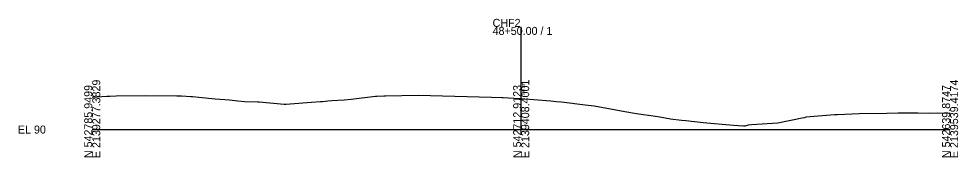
# Model space of a CAD drawing. Extents: x -12831 to 2303, y -10 to 39065.
# Drawn here: x 974.3 to 1302.8, y 36990.3 to 37038.8 of the extents above; entities that cross this region are included whole.
import ezdxf

# ---------------------------------------------------------------- set-up
doc = ezdxf.new("R2010")
doc.units = 0
for name, color, linetype in [('RD_GPK_XS_Cell', 7, 'Continuous'), ('RD_XS_ExGround', 7, 'Continuous'), ('RD_XS_TX_Elev_EX', 7, 'Continuous')]:
    doc.layers.add(name, color=color, linetype=linetype)

msp = doc.modelspace()

# ---------------------------------------------------------------- linework, layer by layer
at = {"layer": 'RD_GPK_XS_Cell'}
for p, q in [((1150, 37000), (1150, 37035.96)), ((1000, 37000), (1150, 37000)), ((1150, 37000), (1300, 37000))]:
    msp.add_line(p, q, dxfattribs=at)
at = {"layer": 'RD_XS_ExGround'}
for p, q in [((1000, 37011.38), (1005.06, 37011.66)), ((1005.06, 37011.66), (1006.15, 37011.72)), ((1006.15, 37011.72), (1008.32, 37011.76)), ((1008.32, 37011.76), (1018.53, 37011.96)), ((1018.53, 37011.96), (1029.58, 37011.85)), ((1029.58, 37011.85), (1031.26, 37011.83)), ((1031.26, 37011.83), (1034.51, 37011.63)), ((1034.51, 37011.63), (1035.1, 37011.57)), ((1035.1, 37011.57), (1037.22, 37011.38)), ((1037.22, 37011.38), (1043.04, 37010.8)), ((1043.04, 37010.8), (1047.94, 37010.37)), ((1047.94, 37010.37), (1050.94, 37010.07)), ((1050.94, 37010.07), (1053.36, 37009.88)), ((1053.36, 37009.88), (1057.89, 37009.71)), ((1057.89, 37009.71), (1058.38, 37009.67)), ((1058.38, 37009.67), (1067.17, 37008.94)), ((1069.16, 37009.03), (1076.66, 37009.55)), ((1076.66, 37009.55), (1079.78, 37009.78)), ((1079.78, 37009.78), (1080.53, 37009.83)), ((1080.53, 37009.83), (1082.44, 37010.09)), ((1082.44, 37010.09), (1083.82, 37010.18)), ((1083.82, 37010.18), (1088.11, 37010.47)), ((1088.11, 37010.47), (1090.5, 37010.67)), ((1090.5, 37010.67), (1099.09, 37011.69)), ((1099.09, 37011.69), (1099.54, 37011.74)), ((1099.54, 37011.74), (1102, 37011.83)), ((1102, 37011.83), (1102.54, 37011.84)), ((1102.54, 37011.84), (1114.01, 37011.99)), ((1114.01, 37011.99), (1139.57, 37011.35)), ((1139.57, 37011.35), (1143.25, 37011.26)), ((1143.25, 37011.26), (1143.73, 37011.23)), ((1143.73, 37011.23), (1149.24, 37010.9)), ((1149.24, 37010.9), (1150, 37010.85)), ((1150, 37010.85), (1151.27, 37010.79)), ((1151.27, 37010.79), (1154.46, 37010.58)), ((1154.46, 37010.58), (1160.37, 37010.04)), ((1160.37, 37010.04), (1162.19, 37009.86)), ((1162.19, 37009.86), (1164.09, 37009.67)), ((1164.09, 37009.67), (1172.42, 37008.7)), ((1067.17, 37008.94), (1067.8, 37008.93)), ((1067.8, 37008.93), (1069.16, 37009.03)), ((1172.42, 37008.7), (1175.57, 37008.3)), ((1175.57, 37008.3), (1182.52, 37007.05)), ((1182.52, 37007.05), (1186.26, 37006.3)), ((1186.26, 37006.3), (1190.35, 37005.58)), ((1190.35, 37005.58), (1197.02, 37004.69)), ((1197.02, 37004.69), (1198.49, 37004.46)), ((1198.49, 37004.46), (1202.23, 37003.8)), ((1202.23, 37003.8), (1206.12, 37003.33)), ((1206.12, 37003.33), (1207.64, 37003.17)), ((1207.64, 37003.17), (1213.67, 37002.5)), ((1239.72, 37002.38), (1248.26, 37004.15)), ((1248.26, 37004.15), (1249.19, 37004.26)), ((1249.19, 37004.26), (1249.69, 37004.4)), ((1249.69, 37004.4), (1259.61, 37005.25)), ((1259.61, 37005.25), (1260.65, 37005.33)), ((1260.65, 37005.33), (1268.26, 37005.57)), ((1268.26, 37005.57), (1277.9, 37005.71)), ((1277.9, 37005.71), (1281.88, 37005.88)), ((1281.88, 37005.88), (1288.67, 37005.82)), ((1288.67, 37005.82), (1292.96, 37005.75)), ((1292.96, 37005.75), (1295.61, 37005.81)), ((1295.61, 37005.81), (1300, 37005.75)), ((1213.67, 37002.5), (1224.22, 37001.54)), ((1224.22, 37001.54), (1227.7, 37001.28)), ((1227.7, 37001.28), (1228.36, 37001.3)), ((1228.36, 37001.3), (1229.55, 37001.7)), ((1229.55, 37001.7), (1230.54, 37001.75)), ((1230.54, 37001.75), (1239.72, 37002.38))]:
    msp.add_line(p, q, dxfattribs=at)

# ---------------------------------------------------------------- texts
at = {"layer": 'RD_GPK_XS_Cell'}
for s, p in [('CHF2', (1140, 37035.96)), ('48+50.00 / 1', (1140, 37033.16)), ('EL 90', (974, 36998.6))]:
    msp.add_text(s, height=2.8, dxfattribs=at).set_placement(p)
for s, p in [('E 2139277.3829', (1002.8, 36990)), ('E 2139408.4001', (1152.8, 36990)), ('E 2139539.4174', (1302.8, 36990)), ('N 542785.9499', (1000, 36990)), ('N 542712.9123', (1150, 36990)), ('N 542639.8747', (1300, 36990))]:
    msp.add_text(s, height=2.8, rotation=90, dxfattribs=at).set_placement(p)
at = {"layer": 'RD_XS_TX_Elev_EX'}
msp.add_text('100.85', height=1, rotation=90, dxfattribs=at).set_placement((1151.25, 37011.85))

doc.saveas('drawing.dxf')
